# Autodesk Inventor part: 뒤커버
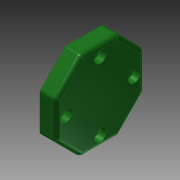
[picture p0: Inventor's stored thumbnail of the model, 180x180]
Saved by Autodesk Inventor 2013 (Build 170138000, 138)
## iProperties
Created: 2015-11
Part Number: 뒤커버
Material: 알루미늄 6061
Document SubType Name: Modeling
Designer: mduedu
Density: 1 g/cm^3
Author: mduedu
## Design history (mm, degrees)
sketch "스케치5" dims "d66" = 60
  geometry: L1 (12.426, 30)-(30, 12.426); L2 (30, 12.426)-(30, -12.426); L3 (30, -12.426)-(12.426, -30); L4 (12.426, -30)-(-12.426, -30); L5 (-12.426, -30)-(-30, -12.426); L6 (-30, -12.426)-(-30, 12.426); L7 (-30, 12.426)-(-12.426, 30); L8 (-12.426, 30)-(12.426, 30); 4 further points
  constraints: 16 end point, 2 coincident, 2 vertical alignment, 1 midpoint, 19 other
extrude "돌출2" new body sketch "스케치5" distance "d67" = 11; taper "d68" = 0 deg
sketch "스케치6"
  geometry: C1 r 16 at (0, 0); 1 further point
  constraints: 1 centre point, 1 coincident
  dimensions: "d69" = 32 diameter of C1
extrude "돌출3" join sketch "스케치6" distance "d70" = 3; taper "d71" = 0 deg
hole "구멍5" diameter "d74" = 25; stored, may be unused: countersink angle "d78" = 90 deg, drill point angle "d80" = 0 deg; dims "d72" = 10, "d73" = 10, "d75" = 6, "d76" = 4, "d77" = 2, "d79" = 10
fillet "모깎기7" dims "d81" = 3
fillet "모깎기8" dims "d82" = 3
fillet "모깎기9" dims "d83" = 3
fillet "모깎기10" dims "d84" = 0.3
sketch "스케치7" dims "d85" = 46
  geometry: 3 further points
  constraints: 2 vertical alignment, 1 coincident, 2 other
hole "구멍6" sketch "스케치7" at (0, 23) diameter "d86" = 4.5; stored, may be unused: countersink angle "d90" = 90 deg, drill point angle "d92" = 0 deg; dims "d87" = 6, "d88" = 8, "d89" = 4.6, "d91" = 10
node "솔리드2"
pattern_circular "원형 패턴3" dims angle "d94" = 360 deg
